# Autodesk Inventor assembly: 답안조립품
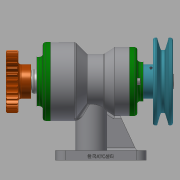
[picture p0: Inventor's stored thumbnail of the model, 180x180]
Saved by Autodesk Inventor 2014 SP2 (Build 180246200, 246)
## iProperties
Created: 2019-01
Part Number: 답안조립품
Document SubType Name: Assembly
Designer: CM-CAD
Author: CM-CAD
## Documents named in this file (15)
- C:\Users\cm\Desktop\490107V1025\답안조립품.iam
- C:\Users\cm\Desktop\490107V1025\본체.ipt
- C:\Users\cm\Desktop\490107V1025\베어링 6203.ipt
- C:\Users\cm\Desktop\490107V1025\베어링 6205.ipt
- C:\Users\cm\Desktop\490107V1025\앞커버.ipt
- C:\Users\cm\Desktop\490107V1025\오일 실 25 38 8.ipt
- C:\Users\cm\Desktop\490107V1025\볼트 M4.ipt
- C:\Users\cm\Desktop\490107V1025\뒤커버.ipt
- C:\Users\cm\Desktop\490107V1025\오일 실 17 30 8.ipt
- C:\Users\cm\Desktop\490107V1025\멈춤나사 M3.ipt
- C:\Users\cm\Desktop\490107V1025\축.ipt
- C:\Users\cm\Desktop\490107V1025\키 6 x 6 x 18.ipt
- C:\Users\cm\Desktop\490107V1025\키 5 x 5 x 20.ipt
- C:\Users\cm\Desktop\490107V1025\스퍼기어.ipt
- C:\Users\cm\Desktop\490107V1025\V-벨트풀리.ipt
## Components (1 placed, 1 different names)
1. V-벨트풀리:1
